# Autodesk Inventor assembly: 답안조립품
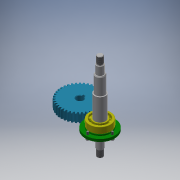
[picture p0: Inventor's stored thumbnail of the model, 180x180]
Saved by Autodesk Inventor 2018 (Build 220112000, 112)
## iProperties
Created: 2023-10
Part Number: 답안조립품
Material: 일반
Document SubType Name: Assembly
Designer: home
Author: home
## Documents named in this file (9)
- C:\Users\home\Desktop\731006V1009\답안조립품.iam
- C:\Users\home\Desktop\731006V1009\본체.ipt
- C:\Users\home\Desktop\731006V1009\베어링 6204.ipt
- C:\Users\home\Desktop\731006V1009\커버.ipt
- C:\Users\home\Desktop\731006V1009\볼트 M4x0.7.ipt
- C:\Users\home\Desktop\731006V1009\오일실 20x35x8.ipt
- C:\Users\home\Desktop\731006V1009\축.ipt
- C:\Users\home\Desktop\731006V1009\키 5x5.ipt
- C:\Users\home\Desktop\731006V1009\스퍼기어.ipt
